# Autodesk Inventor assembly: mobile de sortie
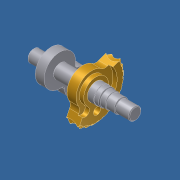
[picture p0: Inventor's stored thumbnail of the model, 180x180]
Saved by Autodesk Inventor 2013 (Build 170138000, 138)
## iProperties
Created: 2011-10
Part Number: mobile de sortie
Document SubType Name: Assembly
Designer: Laur
Author: Laur
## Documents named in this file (5)
- D:\_an13-14\FORMULAIRE_2014\Sujet E4 Poissy 2014\Modélisation_7970_shimano_2014\mobile de sortie.iam
- D:\_an13-14\FORMULAIRE_2014\Sujet E4 Poissy 2014\Modélisation_7970_shimano_2014\arbre de sortie.ipt
- D:\_an13-14\FORMULAIRE_2014\Sujet E4 Poissy 2014\Modélisation_7970_shimano_2014\secteur de roue de vis sans fin.ipt
- D:\_an13-14\FORMULAIRE_2014\Sujet E4 Poissy 2014\Modélisation_7970_shimano_2014\maneton.ipt
- D:\_an13-14\FORMULAIRE_2014\Sujet E4 Poissy 2014\Modélisation_7970_shimano_2014\manivelle.ipt
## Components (4 placed, 4 different names)
1. arbre de sortie:1 — montage manivelle / arbre de sortie, montage secteur denté
2. secteur de roue de vis sans fin:1 — montage secteur denté, pos angulaire relative manivelle / secteur denté
3. maneton:1 — montage maneton / manivelle
4. manivelle:1 — montage maneton / manivelle, montage manivelle / arbre de sortie, pos angulaire relative manivelle / secteur denté
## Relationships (4: Insert 3, Angle 1)
- montage maneton / manivelle [Insert]: maneton:1 ↔ manivelle:1
- montage manivelle / arbre de sortie [Insert]: arbre de sortie:1 ↔ manivelle:1
- montage secteur denté [Insert]: arbre de sortie:1 ↔ secteur de roue de vis sans fin:1
- pos angulaire relative manivelle / secteur denté [Angle]: secteur de roue de vis sans fin:1 ↔ manivelle:1
